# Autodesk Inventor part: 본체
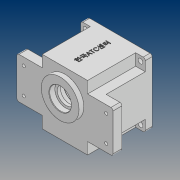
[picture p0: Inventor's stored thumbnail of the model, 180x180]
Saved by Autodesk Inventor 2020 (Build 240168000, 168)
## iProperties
Created: 2020-07
Part Number: 본체
Material: 일반
Document SubType Name: Modeling
Designer: PC312-
Density: 1 g/cm^3
Appearance: 기본값
Mass: 324.89 g
Surface Area: 792.754 cm^2
Volume: 324.89 cm^3
Author: PC312-
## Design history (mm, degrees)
sketch "스케치1"
  geometry: L1 (33, -47)-(-33, -47); L2 (-33, 47)-(33, 47); L3 (33, -47)-(-33, 47); L4 (-33, -47)-(33, 47); L5 (70, -30)-(70, 30); L6 (-70, 30)-(-70, -30); L7 (-70, -30)-(70, 30); L8 (70, -30)-(-70, 30); L9 (70, 30)-(33, 30); L10 (-33, 30)-(-70, 30); L11 (-33, -47)-(-33, -30); L12 (-33, 30)-(-33, 47); L13 (-70, -30)-(-33, -30); L14 (33, -30)-(70, -30); L15 (33, 47)-(33, 30); L16 (33, -30)-(33, -47); 1 further point
  constraints: 32 end point, 10 parallel, 4 midpoint, 4 perpendicular, 3 horizontal
  dimensions: "d0" = 66 distance of L2.start L2.end; "d1" = 94 distance of L2.end L1.start; "d2" = 140 distance of L5.end L6.start; "d3" = 60 distance of L6.start L6.end; "d4" = 33 distance from line of point (0, 0) L15; "d5" = 30 distance from line of point (0, 0) L9; "d6" = 47 distance from line of point (0, 0) L1; "d7" = 70 distance from line of point (0, 0) L6
extrude "돌출1" new body sketch "스케치1" distance "d8" = 13; taper "d9" = 0 deg
sketch "스케치2"
  geometry: L1 (-47, -47)-(47, -47); L2 (47, -47)-(47, 47); L3 (47, 47)-(-47, 47); L4 (-47, 47)-(-47, -47); L5 (-47, -47)-(47, 47); L6 (47, -47)-(-47, 47); 1 further point
  constraints: 12 end point, 2 midpoint, 2 parallel, 1 horizontal, 1 perpendicular
  dimensions: "d10" = 94 distance of L3.end L2.end; "d11" = 94 distance of L2.end L1.end
extrude "돌출2" join sketch "스케치2" distance "d12" = 67; taper "d13" = 0 deg
sketch "스케치3"
  geometry: L1 (33, 30)-(47, 30) reference; L2 (47, 47)-(47, 30) reference; L3 (33, 47)-(47, 47) reference; L4 (33, 47)-(33, 30) reference; L5 (-33, 30)-(-33, 47) reference; L6 (-47, 47)-(-33, 47) reference; L7 (-47, 30)-(-47, 47) reference; L8 (-47, 30)-(-33, 30) reference; L9 (-33, -47)-(-33, -30) reference; L10 (-33, -30)-(-47, -30) reference; L11 (-47, -47)-(-47, -30) reference; L12 (-33, -47)-(-47, -47) reference; L13 (47, -30)-(33, -30) reference; L14 (33, -30)-(33, -47) reference; L15 (47, -47)-(33, -47) reference; L16 (47, -30)-(47, -47) reference; 1 further point
extrude "돌출3" cut sketch "스케치3" distance "d14" = 57; taper "d15" = 0 deg
sketch "스케치4"
  geometry: C1 r 27.5 at (0, 11); 1 further point
  constraints: 1 centre point, 1 vertical alignment
  dimensions: "d16" = 55 diameter of C1; "d17" = 11 distance of point (0, 0) C1.centre
extrude "돌출4" join sketch "스케치4" distance "d18" = 7; taper "d19" = 0 deg
sketch "스케치5"
  geometry: C1 r 27.5 at (0, 0) reference; C2 r 16 at (0, 0); 1 further point
  constraints: 1 centre point, 1 coincident
  dimensions: "d20" = 32 diameter of C2
extrude "돌출5" cut sketch "스케치5" distance "d21" = 8.3; taper "d22" = 0 deg
sketch "스케치6"
  geometry: C1 r 16 at (0, 0) reference; C2 r 12.5 at (0, 0); 1 further point
  constraints: 1 centre point, 1 coincident
  dimensions: "d23" = 25 diameter of C2
sketch "스케치7"
  geometry: C1 r 43 at (0, 0); 1 further point
  constraints: 1 centre point, 1 coincident
  dimensions: "d24" = 86 diameter of C1
extrude "돌출6" cut sketch "스케치7" distance "d25" = 9; taper "d26" = 0 deg
sketch "스케치8"
  geometry: C1 r 40 at (0, 0); 1 further point
  constraints: 1 centre point, 1 coincident
  dimensions: "d27" = 80 diameter of C1
extrude "돌출7" cut sketch "스케치8" distance "d28" = 62; taper "d29" = 0 deg
extrude "돌출8" cut sketch "스케치6" distance "d30" = 4.7; taper "d31" = 0 deg
sketch "스케치9"
  geometry: C1 r 27.5 at (0, 0) reference; C2 r 17.5 at (0, 0); 1 further point
  constraints: 1 centre point, 1 coincident
  dimensions: "d32" = 35 diameter of C2
extrude "돌출9" cut sketch "스케치9" distance "d33" = 10; taper "d34" = 0 deg
sketch "스케치12"
  geometry: C1 r 17.5 at (0, 11) reference; C2 r 11 at (0, -20) reference; A1 r 21 centre (0, 11) between (8.978, -7.984) and (-8.978, -7.984); A2 r 15 centre (0, -20) between (-8.978, -7.984) and (8.978, -7.984); 1 further point
  constraints: 4 point on circle, 2 centre point, 2 coincident
  dimensions: "d42" = 42 diameter of A1; "d43" = 30 diameter of A2
extrude "돌출12" join sketch "스케치12" distance "d44" = 7; taper "d45" = 0 deg
sketch "스케치13"
  geometry: A1 r 36 centre (0, 0) between (-36, 0) and (-35.778, -3.995); A2 r 4 centre (-36, 0) between (-35.852, -3.997) and (-35.852, 3.997); A3 r 3.5 centre (-35.722, -7.495) between (-35.778, -3.995) and (-39.148, -8.214); A4 r 3.5 centre (-35.722, 7.495) between (-39.148, 8.214) and (-35.778, 3.995); A5 r 40 centre (0, 0) between (-39.148, -8.214) and (-39.148, 8.214) reference; 1 further point
  constraints: 13 point on circle, 4 centre point, 4 tangent, 1 coincident, 1 horizontal alignment
  dimensions: "d46" = 72 diameter of A1; "d47" = 8 diameter of A2; "d48" = 7 diameter of A3; "d49" = 7 diameter of A4
extrude "돌출13" join sketch "스케치13" stored distance "d50" = 7; taper "d51" = 0 deg
sketch "스케치14"
  geometry: A1 r 4 centre (-36, 0) between (-35.852, -3.997) and (-35.852, 3.997) reference; 2 further points
  constraints: 1 coincident
hole "구멍1" sketch "스케치14" at (-36, 0) diameter "d52" = 3.242; stored, may be unused: countersink angle "d56" = 90 deg, drill point angle "d58" = 118 deg; dims "d53" = 7, "d54" = 4, "d55" = 2, "d57" = 9
sketch "스케치15"
  geometry: C1 r 11 at (0, 0) reference; C2 r 9.5 at (0, 0); 1 further point
  constraints: 1 centre point, 1 coincident
  dimensions: "d59" = 19 diameter of C2
extrude "돌출14" cut sketch "스케치15" distance "d60" = 3; taper "d61" = 0 deg
sketch "스케치16"
  geometry: L1 (-47, 30)-(-70, 30) reference; L2 (-70, 30)-(-70, -30) reference; L3 (-70, -30)-(-47, -30) reference; 2 further points
  dimensions: "d62" = 11 distance from line of L1 point (-60, 19); "d63" = 10 distance from line of L2 point (-60, 19)
hole "구멍2" sketch "스케치16" at (-60, 19) diameter "d66" = 4.5; stored, may be unused: countersink angle "d70" = 90 deg, drill point angle "d72" = 118 deg; dims "d67" = 7, "d68" = 10, "d69" = 5, "d71" = 9
sketch "스케치17"
  geometry: L1 (47, 47)-(47, 30) reference; L2 (70, 30)-(33, 30) reference; 2 further points
  dimensions: "d79" = 7 distance from line of L1 point (40, 40); "d80" = 10 distance from line of L2 point (40, 40)
hole "구멍3" sketch "스케치17" at (40, 40) diameter "d81" = 7; stored, may be unused: countersink angle "d85" = 90 deg, drill point angle "d87" = 118 deg; dims "d82" = 7, "d83" = 10, "d84" = 5, "d86" = 9
fillet "모깎기1" dims "d94" = 3
chamfer "모따기1" distance "d95" = 1; stored, may be unused: second distance "d96" = 2, angle "d97" = 45 deg
fillet "모깎기3" dims "d99" = 3
chamfer "모따기2" distance "d100" = 0.8; stored, may be unused: second distance "d101" = 2, angle "d102" = 30 deg
fillet "모깎기4" dims "d103" = 3
chamfer "모따기3" distance "d104" = 1; stored, may be unused: second distance "d105" = 2, angle "d106" = 30 deg
node "작업 평면1"
sketch "스케치18"
  geometry: L1 (-11, 80)-(77, 80) reference; 2 further points
  constraints: 1 vertical alignment, 1 other
  dimensions: "d108" = 40 distance from line of L1 point (33, 40)
feature "엠보싱1" sketch "스케치18" dims "d0" = 66, "d1" = 94, "d2" = 140, "d3" = 60, "d4" = 33, "d5" = 30, "d6" = 47, "d7" = 70, "d10" = 94, "d11" = 94, "d109" = 0.5, "d110" = 0
node "솔리드1"
mirror "미러1"
pattern_linear "직사각형 패턴1" dims "d75" = 38, "d78" = 120
pattern_linear "직사각형 패턴2" dims "d90" = 80, "d93" = 80
node "투영된 루프1"
node "투영된 루프2"
node "투영된 루프3"
node "투영된 루프4"
feature "A9D066F2-1C7D-4E18-AEED-F7BC21143FA4" dims "d66" = 4.5, "d67" = 7, "d68" = 10, "d69" = 5, "d70" = 90 deg, "d71" = 9, "d72" = 118 deg
